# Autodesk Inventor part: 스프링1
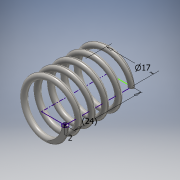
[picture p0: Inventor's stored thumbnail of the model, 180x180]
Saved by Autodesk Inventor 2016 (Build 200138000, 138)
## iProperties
Created: 2019-11
Part Number: 스프링1
Material: 스테인레스 스틸
Document SubType Name: Modeling
Designer: user
Mass: 6.57569 g
Surface Area: 16.7185 cm^2
Volume: 0.821961 cm^3
Density: 8 g/cm^3
Appearance: 반연마
Author: user
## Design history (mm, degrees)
sketch "스케치1"
  geometry: L1 (0, 0)-(8.5, 0); L2 (8.5, 0)-(8.5, 20.5); L3 (8.5, 20.5)-(0, 20.5); L4 (0, 20.5)-(0, 0); C1 r 1 at (8.5, 0)
  constraints: 8 end point, 2 parallel, 1 centre point, 1 coincident, 1 horizontal, 1 perpendicular
  dimensions: "d0" = 20.5 distance between parallel lines of L1 L3 (derived); "d1" = 17 diameter of L2 L4; "d2" = 2 diameter of C1
feature "코일1" sketch "스케치1" pitch "d3" = 10; turns "d5" = 5; dims "d4" = 20.5 (= d0), "d6" = 0, angle "d7" = 90 deg, angle "d8" = 90 deg, "d9" = 0, "d10" = 0
sketch "스케치2"
  geometry: L1 (0, 14.377)-(20.5, 14.377); L2 (20.5, 14.377)-(20.5, -14.377); L3 (20.5, -14.377)-(0, -14.377); L4 (0, -14.377)-(0, 14.377); 2 further points
  constraints: 8 end point, 2 parallel, 1 coincident, 1 horizontal, 1 midpoint, 1 perpendicular
  dimensions: "d11" = 28.75382 distance of L1.end L2.end; "d12" = 20.5 distance between parallel lines of L4 L2 (= d0)
extrude "돌출1" sketch "스케치2" stored distance "d13" = 26.25; taper "d14" = 0 deg
node "솔리드1"
